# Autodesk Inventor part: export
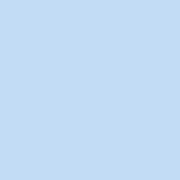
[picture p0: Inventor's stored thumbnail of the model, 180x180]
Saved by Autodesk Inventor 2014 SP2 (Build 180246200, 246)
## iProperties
Created: 2016-11
Part Number: export
Material: Ocel
Document SubType Name: Modeling
Designer: j.sohajek
Density: 7.85 g/cm^3
Appearance: Ocel
Company: Sigma Group a.s.
Author: j.sohajek
Revision Number: 1
HMOTNOST: 0
14 Skl.č. kusovník: =<05 Skladová položka><14 Skl.č. polotovaru bez výkr.>
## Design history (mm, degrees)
